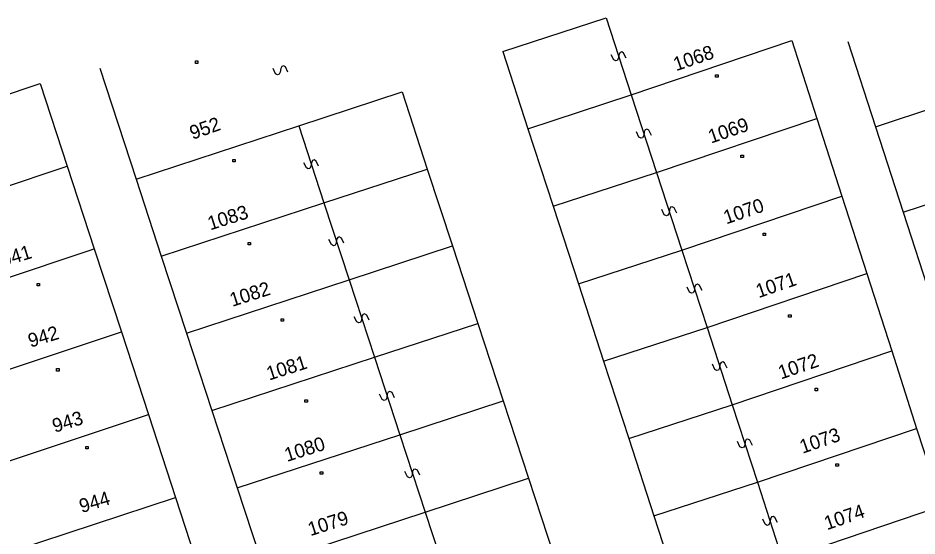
# Model space of a CAD drawing. Extents: x -493352 to -492964, y -1127001 to -1126712.
# Drawn here: x -493269.27 to -493236.25, y -1126731.23 to -1126712.19 of the extents above; entities that cross this region are included whole.
import ezdxf

# ---------------------------------------------------------------- set-up
doc = ezdxf.new("R2010")
doc.units = 0
doc.layers.add('katastrální mapa', color=7, linetype='Continuous')

msp = doc.modelspace()

# ---------------------------------------------------------------- linework, layer by layer
at = {"layer": 'katastrální mapa'}
for p, q in [((-493251.47, -1126713.42), (-493247.67, -1126712.19)), ((-493247.67, -1126712.19), (-493246.75, -1126715.02)), ((-493246.75, -1126715.02), (-493240.85, -1126713.02)), ((-493240.85, -1126713.02), (-493239.93, -1126715.88)), ((-493238.79, -1126713.05), (-493237.78, -1126716.19)), ((-493251.47, -1126713.42), (-493250.55, -1126716.26)), ((-493247.39, -1126713.73), (-493247.48, -1126713.54)), ((-493247.32, -1126713.77), (-493247.39, -1126713.73)), ((-493247.22, -1126713.67), (-493247.26, -1126713.75)), ((-493247.2, -1126713.54), (-493247.22, -1126713.67)), ((-493247.16, -1126713.46), (-493247.2, -1126713.54)), ((-493247.1, -1126713.44), (-493247.16, -1126713.46)), ((-493247.03, -1126713.48), (-493247.1, -1126713.44)), ((-493246.94, -1126713.67), (-493247.03, -1126713.48)), ((-493266.27, -1126714.03), (-493264.93, -1126718.12)), ((-493262.75, -1126713.77), (-493262.66, -1126713.77)), ((-493262.75, -1126713.86), (-493262.75, -1126713.77)), ((-493262.66, -1126713.86), (-493262.75, -1126713.86)), ((-493262.66, -1126713.77), (-493262.66, -1126713.86)), ((-493259.81, -1126714.24), (-493259.9, -1126714.05)), ((-493259.62, -1126714.05), (-493259.64, -1126714.18)), ((-493259.58, -1126713.97), (-493259.62, -1126714.05)), ((-493259.52, -1126713.95), (-493259.58, -1126713.97)), ((-493259.45, -1126713.99), (-493259.52, -1126713.95)), ((-493259.36, -1126714.18), (-493259.45, -1126713.99)), ((-493247.26, -1126713.75), (-493247.32, -1126713.77)), ((-493259.74, -1126714.28), (-493259.81, -1126714.24)), ((-493259.68, -1126714.26), (-493259.74, -1126714.28)), ((-493259.64, -1126714.18), (-493259.68, -1126714.26)), ((-493243.65, -1126714.28), (-493243.56, -1126714.28)), ((-493243.65, -1126714.37), (-493243.65, -1126714.28)), ((-493243.56, -1126714.37), (-493243.65, -1126714.37)), ((-493243.56, -1126714.28), (-493243.56, -1126714.37)), ((-493237.78, -1126716.19), (-493231.9, -1126714.23)), ((-493274.39, -1126716.57), (-493268.45, -1126714.6)), ((-493268.45, -1126714.6), (-493267.46, -1126717.64)), ((-493258.96, -1126716.16), (-493255.16, -1126714.91)), ((-493255.16, -1126714.91), (-493254.24, -1126717.75)), ((-493250.55, -1126716.26), (-493246.75, -1126715.02)), ((-493246.75, -1126715.02), (-493245.82, -1126717.87)), ((-493245.82, -1126717.87), (-493239.93, -1126715.88)), ((-493239.93, -1126715.88), (-493239.02, -1126718.74)), ((-493264.93, -1126718.12), (-493258.96, -1126716.16)), ((-493258.96, -1126716.16), (-493258.04, -1126718.99)), ((-493250.55, -1126716.26), (-493249.62, -1126719.11)), ((-493246.47, -1126716.57), (-493246.56, -1126716.38)), ((-493246.28, -1126716.38), (-493246.29, -1126716.51)), ((-493246.24, -1126716.3), (-493246.28, -1126716.38)), ((-493246.18, -1126716.28), (-493246.24, -1126716.3)), ((-493246.1, -1126716.32), (-493246.18, -1126716.28)), ((-493246.01, -1126716.51), (-493246.1, -1126716.32)), ((-493237.78, -1126716.19), (-493236.76, -1126719.33)), ((-493246.39, -1126716.61), (-493246.47, -1126716.57)), ((-493246.33, -1126716.59), (-493246.39, -1126716.61)), ((-493246.29, -1126716.51), (-493246.33, -1126716.59)), ((-493242.72, -1126717.23), (-493242.63, -1126717.23)), ((-493242.72, -1126717.32), (-493242.72, -1126717.23)), ((-493242.63, -1126717.32), (-493242.72, -1126717.32)), ((-493242.63, -1126717.23), (-493242.63, -1126717.32)), ((-493236.76, -1126719.33), (-493230.87, -1126717.37)), ((-493273.4, -1126719.61), (-493267.46, -1126717.64)), ((-493267.46, -1126717.64), (-493266.47, -1126720.68)), ((-493261.38, -1126717.39), (-493261.29, -1126717.39)), ((-493261.38, -1126717.48), (-493261.38, -1126717.39)), ((-493261.29, -1126717.48), (-493261.38, -1126717.48)), ((-493261.29, -1126717.39), (-493261.29, -1126717.48)), ((-493258.68, -1126717.7), (-493258.77, -1126717.51)), ((-493258.61, -1126717.74), (-493258.68, -1126717.7)), ((-493258.51, -1126717.64), (-493258.55, -1126717.72)), ((-493258.49, -1126717.51), (-493258.51, -1126717.64)), ((-493258.45, -1126717.43), (-493258.49, -1126717.51)), ((-493258.39, -1126717.41), (-493258.45, -1126717.43)), ((-493258.32, -1126717.45), (-493258.39, -1126717.41)), ((-493258.23, -1126717.64), (-493258.32, -1126717.45)), ((-493258.55, -1126717.72), (-493258.61, -1126717.74)), ((-493258.04, -1126718.99), (-493254.24, -1126717.75)), ((-493254.24, -1126717.75), (-493253.31, -1126720.57)), ((-493249.62, -1126719.11), (-493245.82, -1126717.87)), ((-493245.82, -1126717.87), (-493244.89, -1126720.72)), ((-493264.93, -1126718.12), (-493264.01, -1126720.95)), ((-493264.01, -1126720.95), (-493258.04, -1126718.99)), ((-493258.04, -1126718.99), (-493257.11, -1126721.81)), ((-493244.89, -1126720.72), (-493239.02, -1126718.74)), ((-493239.02, -1126718.74), (-493238.1, -1126721.58)), ((-493249.62, -1126719.11), (-493248.69, -1126721.96)), ((-493245.54, -1126719.42), (-493245.63, -1126719.23)), ((-493245.35, -1126719.23), (-493245.36, -1126719.36)), ((-493245.31, -1126719.15), (-493245.35, -1126719.23)), ((-493245.25, -1126719.13), (-493245.31, -1126719.15)), ((-493245.17, -1126719.17), (-493245.25, -1126719.13)), ((-493245.08, -1126719.36), (-493245.17, -1126719.17)), ((-493236.76, -1126719.33), (-493235.75, -1126722.47)), ((-493245.46, -1126719.46), (-493245.54, -1126719.42)), ((-493245.4, -1126719.44), (-493245.46, -1126719.46)), ((-493245.36, -1126719.36), (-493245.4, -1126719.44)), ((-493257.76, -1126720.52), (-493257.85, -1126720.33)), ((-493257.57, -1126720.33), (-493257.58, -1126720.47)), ((-493257.53, -1126720.26), (-493257.57, -1126720.33)), ((-493257.47, -1126720.24), (-493257.53, -1126720.26)), ((-493257.39, -1126720.28), (-493257.47, -1126720.24)), ((-493257.3, -1126720.47), (-493257.39, -1126720.28)), ((-493241.91, -1126720.1), (-493241.82, -1126720.1)), ((-493241.91, -1126720.19), (-493241.91, -1126720.1)), ((-493241.82, -1126720.19), (-493241.91, -1126720.19)), ((-493241.82, -1126720.1), (-493241.82, -1126720.19)), ((-493260.82, -1126720.44), (-493260.73, -1126720.44)), ((-493260.82, -1126720.53), (-493260.82, -1126720.44)), ((-493260.73, -1126720.53), (-493260.82, -1126720.53)), ((-493260.73, -1126720.44), (-493260.73, -1126720.53)), ((-493257.68, -1126720.56), (-493257.76, -1126720.52)), ((-493257.62, -1126720.54), (-493257.68, -1126720.56)), ((-493257.58, -1126720.47), (-493257.62, -1126720.54)), ((-493257.11, -1126721.81), (-493253.31, -1126720.57)), ((-493253.31, -1126720.57), (-493252.38, -1126723.42)), ((-493272.41, -1126722.65), (-493266.47, -1126720.68)), ((-493266.47, -1126720.68), (-493265.47, -1126723.73)), ((-493264.01, -1126720.95), (-493263.08, -1126723.78)), ((-493248.69, -1126721.96), (-493244.89, -1126720.72)), ((-493244.89, -1126720.72), (-493243.96, -1126723.57)), ((-493243.96, -1126723.57), (-493238.1, -1126721.58)), ((-493238.1, -1126721.58), (-493237.18, -1126724.43)), ((-493268.57, -1126721.95), (-493268.48, -1126721.95)), ((-493268.57, -1126722.04), (-493268.57, -1126721.95)), ((-493268.48, -1126721.95), (-493268.48, -1126722.04)), ((-493263.08, -1126723.78), (-493257.11, -1126721.81)), ((-493257.11, -1126721.81), (-493256.18, -1126724.66)), ((-493248.69, -1126721.96), (-493247.77, -1126724.81)), ((-493244.32, -1126721.98), (-493244.38, -1126722)), ((-493244.24, -1126722.02), (-493244.32, -1126721.98)), ((-493268.48, -1126722.04), (-493268.57, -1126722.04)), ((-493244.61, -1126722.27), (-493244.7, -1126722.08)), ((-493244.53, -1126722.31), (-493244.61, -1126722.27)), ((-493244.47, -1126722.29), (-493244.53, -1126722.31)), ((-493244.43, -1126722.21), (-493244.47, -1126722.29)), ((-493244.42, -1126722.08), (-493244.43, -1126722.21)), ((-493244.38, -1126722), (-493244.42, -1126722.08)), ((-493244.15, -1126722.21), (-493244.24, -1126722.02)), ((-493259.61, -1126723.25), (-493259.52, -1126723.25)), ((-493259.61, -1126723.34), (-493259.61, -1126723.25)), ((-493259.52, -1126723.25), (-493259.52, -1126723.34)), ((-493256.83, -1126723.36), (-493256.92, -1126723.17)), ((-493256.65, -1126723.3), (-493256.69, -1126723.38)), ((-493256.64, -1126723.17), (-493256.65, -1126723.3)), ((-493256.6, -1126723.09), (-493256.64, -1126723.17)), ((-493256.54, -1126723.07), (-493256.6, -1126723.09)), ((-493256.46, -1126723.11), (-493256.54, -1126723.07)), ((-493256.37, -1126723.3), (-493256.46, -1126723.11)), ((-493240.97, -1126723.1), (-493240.88, -1126723.1)), ((-493240.97, -1126723.19), (-493240.97, -1126723.1)), ((-493240.88, -1126723.19), (-493240.97, -1126723.19)), ((-493240.88, -1126723.1), (-493240.88, -1126723.19)), ((-493259.52, -1126723.34), (-493259.61, -1126723.34)), ((-493256.75, -1126723.4), (-493256.83, -1126723.36)), ((-493256.69, -1126723.38), (-493256.75, -1126723.4)), ((-493256.18, -1126724.66), (-493252.38, -1126723.42)), ((-493252.38, -1126723.42), (-493251.45, -1126726.26)), ((-493247.77, -1126724.81), (-493243.96, -1126723.57)), ((-493243.96, -1126723.57), (-493243.04, -1126726.41)), ((-493271.41, -1126725.7), (-493265.47, -1126723.73)), ((-493265.47, -1126723.73), (-493264.48, -1126726.77)), ((-493263.08, -1126723.78), (-493262.15, -1126726.62)), ((-493243.04, -1126726.41), (-493237.18, -1126724.43)), ((-493237.18, -1126724.43), (-493236.27, -1126727.28)), ((-493262.15, -1126726.62), (-493256.18, -1126724.66)), ((-493256.18, -1126724.66), (-493255.25, -1126727.51)), ((-493247.77, -1126724.81), (-493246.84, -1126727.65)), ((-493243.68, -1126725.11), (-493243.77, -1126724.92)), ((-493243.49, -1126724.92), (-493243.51, -1126725.06)), ((-493243.45, -1126724.85), (-493243.49, -1126724.92)), ((-493243.39, -1126724.83), (-493243.45, -1126724.85)), ((-493243.32, -1126724.87), (-493243.39, -1126724.83)), ((-493243.23, -1126725.06), (-493243.32, -1126724.87)), ((-493267.85, -1126725.08), (-493267.76, -1126725.08)), ((-493267.85, -1126725.17), (-493267.85, -1126725.08)), ((-493267.76, -1126725.17), (-493267.85, -1126725.17)), ((-493267.76, -1126725.08), (-493267.76, -1126725.17)), ((-493243.61, -1126725.15), (-493243.68, -1126725.11)), ((-493243.55, -1126725.13), (-493243.61, -1126725.15)), ((-493243.51, -1126725.06), (-493243.55, -1126725.13)), ((-493255.67, -1126725.94), (-493255.71, -1126726.02)), ((-493255.61, -1126725.92), (-493255.67, -1126725.94)), ((-493255.53, -1126725.96), (-493255.61, -1126725.92)), ((-493240, -1126725.8), (-493239.91, -1126725.8)), ((-493240, -1126725.89), (-493240, -1126725.8)), ((-493239.91, -1126725.89), (-493240, -1126725.89)), ((-493239.91, -1126725.8), (-493239.91, -1126725.89)), ((-493258.73, -1126726.22), (-493258.64, -1126726.22)), ((-493258.73, -1126726.31), (-493258.73, -1126726.22)), ((-493258.64, -1126726.22), (-493258.64, -1126726.31)), ((-493255.9, -1126726.21), (-493255.99, -1126726.02)), ((-493255.82, -1126726.25), (-493255.9, -1126726.21)), ((-493255.76, -1126726.23), (-493255.82, -1126726.25)), ((-493255.72, -1126726.15), (-493255.76, -1126726.23)), ((-493255.71, -1126726.02), (-493255.72, -1126726.15)), ((-493255.44, -1126726.15), (-493255.53, -1126725.96)), ((-493255.25, -1126727.51), (-493251.45, -1126726.26)), ((-493251.45, -1126726.26), (-493250.52, -1126729.1)), ((-493258.64, -1126726.31), (-493258.73, -1126726.31)), ((-493246.84, -1126727.65), (-493243.04, -1126726.41)), ((-493243.04, -1126726.41), (-493242.11, -1126729.25)), ((-493270.42, -1126728.74), (-493264.48, -1126726.77)), ((-493264.48, -1126726.77), (-493263.49, -1126729.81)), ((-493262.15, -1126726.62), (-493261.22, -1126729.46)), ((-493261.22, -1126729.46), (-493255.25, -1126727.51)), ((-493255.25, -1126727.51), (-493254.32, -1126730.35)), ((-493242.11, -1126729.25), (-493236.27, -1126727.28)), ((-493236.27, -1126727.28), (-493235.35, -1126730.12)), ((-493246.84, -1126727.65), (-493245.92, -1126730.49)), ((-493242.76, -1126727.95), (-493242.85, -1126727.76)), ((-493242.58, -1126727.9), (-493242.62, -1126727.97)), ((-493242.57, -1126727.76), (-493242.58, -1126727.9)), ((-493242.53, -1126727.69), (-493242.57, -1126727.76)), ((-493242.47, -1126727.67), (-493242.53, -1126727.69)), ((-493242.39, -1126727.71), (-493242.47, -1126727.67)), ((-493242.3, -1126727.9), (-493242.39, -1126727.71)), ((-493266.78, -1126727.94), (-493266.69, -1126727.94)), ((-493266.78, -1126728.03), (-493266.78, -1126727.94)), ((-493266.69, -1126728.03), (-493266.78, -1126728.03)), ((-493266.69, -1126727.94), (-493266.69, -1126728.03)), ((-493242.68, -1126727.99), (-493242.76, -1126727.95)), ((-493242.62, -1126727.97), (-493242.68, -1126727.99)), ((-493239.23, -1126728.58), (-493239.14, -1126728.58)), ((-493239.23, -1126728.67), (-493239.23, -1126728.58)), ((-493239.14, -1126728.58), (-493239.14, -1126728.67)), ((-493258.17, -1126728.87), (-493258.08, -1126728.87)), ((-493258.17, -1126728.96), (-493258.17, -1126728.87)), ((-493258.08, -1126728.87), (-493258.08, -1126728.96)), ((-493254.97, -1126729.05), (-493255.06, -1126728.86)), ((-493254.78, -1126728.86), (-493254.79, -1126729)), ((-493254.74, -1126728.79), (-493254.78, -1126728.86)), ((-493254.68, -1126728.77), (-493254.74, -1126728.79)), ((-493254.6, -1126728.81), (-493254.68, -1126728.77)), ((-493254.51, -1126729), (-493254.6, -1126728.81)), ((-493239.14, -1126728.67), (-493239.23, -1126728.67)), ((-493258.08, -1126728.96), (-493258.17, -1126728.96)), ((-493254.89, -1126729.09), (-493254.97, -1126729.05)), ((-493254.83, -1126729.07), (-493254.89, -1126729.09)), ((-493254.79, -1126729), (-493254.83, -1126729.07)), ((-493254.32, -1126730.35), (-493250.52, -1126729.1)), ((-493250.52, -1126729.1), (-493249.59, -1126731.95)), ((-493245.92, -1126730.49), (-493242.11, -1126729.25)), ((-493242.11, -1126729.25), (-493241.19, -1126732.1)), ((-493261.22, -1126729.46), (-493260.29, -1126732.31)), ((-493269.43, -1126731.78), (-493263.49, -1126729.81)), ((-493263.49, -1126729.81), (-493262.5, -1126732.85)), ((-493241.19, -1126732.1), (-493235.35, -1126730.12)), ((-493260.29, -1126732.31), (-493254.32, -1126730.35)), ((-493254.32, -1126730.35), (-493253.39, -1126733.19)), ((-493245.92, -1126730.49), (-493244.99, -1126733.34)), ((-493241.6, -1126730.53), (-493241.64, -1126730.61)), ((-493241.54, -1126730.51), (-493241.6, -1126730.53)), ((-493241.47, -1126730.55), (-493241.54, -1126730.51)), ((-493241.38, -1126730.74), (-493241.47, -1126730.55)), ((-493241.83, -1126730.8), (-493241.92, -1126730.61)), ((-493241.76, -1126730.84), (-493241.83, -1126730.8)), ((-493241.7, -1126730.82), (-493241.76, -1126730.84)), ((-493241.66, -1126730.74), (-493241.7, -1126730.82)), ((-493241.64, -1126730.61), (-493241.66, -1126730.74))]:
    msp.add_line(p, q, dxfattribs=at)

# ---------------------------------------------------------------- texts
for s, rotation, p in [('1068', 19.026, (-493245.1, -1126714.15)), ('952', 19.368, (-493262.86, -1126716.67)), ('1069', 19.026, (-493243.82, -1126716.81)), ('1070', 19.026, (-493243.26, -1126719.78)), ('1083', 17.703, (-493262.21, -1126720)), ('941', 17.073, (-493269.81, -1126721.34)), ('1071', 19.026, (-493242.07, -1126722.49)), ('1082', 17.703, (-493261.4, -1126722.81)), ('942', 17.073, (-493268.81, -1126724.31)), ('1081', 17.703, (-493260.05, -1126725.52)), ('1072', 19.026, (-493241.25, -1126725.48)), ('943', 17.073, (-493267.92, -1126727.44)), ('1073', 19.026, (-493240.46, -1126728.21)), ('1080', 17.703, (-493259.39, -1126728.51)), ('944', 17.073, (-493266.93, -1126730.39)), ('1074', 19.026, (-493239.56, -1126731.02)), ('1079', 17.703, (-493258.53, -1126731.24))]:
    msp.add_text(s, height=0.51, rotation=rotation, dxfattribs=at).set_placement(p)

doc.saveas('drawing.dxf')
